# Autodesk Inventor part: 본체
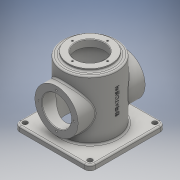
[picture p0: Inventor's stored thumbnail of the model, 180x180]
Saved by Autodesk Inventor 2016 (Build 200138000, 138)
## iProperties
Created: 2019-08
Part Number: 본체
Material: 일반
Document SubType Name: Modeling
Designer: user
Density: 1 g/cm^3
Appearance: 기본값
Author: user
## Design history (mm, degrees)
sketch "스케치1"
  geometry: L1 (70, -70)-(-70, -70); L2 (-70, -70)-(-70, 70); L3 (-70, 70)-(70, 70); L4 (70, 70)-(70, -70); L5 (70, -70)-(-70, 70); L6 (-70, -70)-(70, 70); 1 further point
  constraints: 12 end point, 2 midpoint, 2 parallel, 1 horizontal, 1 perpendicular
  dimensions: "d0" = 140 distance of L2.end L3.end; "d1" = 140 distance of L1.end L2.end
extrude "돌출1" new body sketch "스케치1" distance "d2" = 10; taper "d3" = 0 deg
sketch "스케치2"
  geometry: C1 r 50 at (0, 0); 1 further point
  constraints: 1 centre point, 1 coincident
  dimensions: "d4" = 100 diameter of C1
extrude "돌출2" join sketch "스케치2" distance "d5" = 110; taper "d6" = 0 deg
sketch "스케치3"
  geometry: C1 r 40 at (0, 0); 1 further point
  constraints: 1 centre point, 1 coincident
  dimensions: "d7" = 80 diameter of C1
extrude "돌출3" join sketch "스케치3" distance "d8" = 5; taper "d9" = 0 deg
sketch "스케치6"
  geometry: C1 r 27 at (0, 0); 1 further point
  constraints: 1 centre point, 1 coincident
  dimensions: "d11" = 54 diameter of C1
hole "구멍1" sketch "스케치6" at (0, 0) diameter "d12" = 54; stored, may be unused: countersink angle "d16" = 90 deg, drill point angle "d18" = 0 deg; dims "d13" = 6, "d14" = 4, "d15" = 2, "d17" = 13
node "작업 평면1"
sketch "스케치9"
  geometry: L1 (-70, 0)-(70, 0) reference; C1 r 40 at (0, 60); 2 further points
  constraints: 1 centre point, 1 midpoint, 1 vertical alignment
  dimensions: "d28" = 80 diameter of C1; "d29" = 60 distance from line of L1 C1.centre
extrude "돌출4" join sketch "스케치9" stored distance "d30" = 12; taper "d31" = 0 deg
fillet "모깎기1" dims "d32" = 10
hole "구멍3" diameter "d35" = 9; stored, may be unused: countersink angle "d39" = 90 deg, drill point angle "d41" = 0 deg; dims "d33" = 10, "d34" = 10, "d36" = 6, "d37" = 4, "d38" = 2, "d40" = 112
sketch "스케치12"
  geometry: 2 further points
  constraints: 1 vertical alignment
  dimensions: "d49" = 32.5 distance of point (0, 0) point (0, 32.5)
hole "구멍4" sketch "스케치12" at (0, 32.5) diameter "d50" = 3.242; stored, may be unused: countersink angle "d54" = 90 deg, drill point angle "d56" = 118 deg; dims "d51" = 8, "d52" = 4, "d53" = 2, "d55" = 10
fillet "모깎기2" dims "d60" = 3
fillet "모깎기3" dims "d61" = 3
hole "구멍5" diameter "d64" = 54; stored, may be unused: countersink angle "d68" = 90 deg, drill point angle "d70" = 0 deg; dims "d62" = 10, "d63" = 10, "d65" = 8, "d66" = 4, "d67" = 2, "d69" = 10
sketch "스케치15"
  geometry: C1 r 27 at (0, 0) reference; C2 r 40 at (0, 0) reference; 2 further points
  constraints: 1 vertical alignment
  dimensions: "d71" = 32.5 distance of C1.centre point (0, 32.5)
hole "구멍6" sketch "스케치15" at (0, 32.5) diameter "d72" = 3.242; stored, may be unused: countersink angle "d76" = 90 deg, drill point angle "d78" = 118 deg; dims "d73" = 8, "d74" = 4, "d75" = 2, "d77" = 10
fillet "모깎기4" dims "d82" = 3
chamfer "모따기1" distance "d83" = 1; stored, may be unused: second distance "d84" = 2, angle "d85" = 45 deg
sketch "스케치17"
  geometry: C1 r 45 at (0, 0); 1 further point
  constraints: 1 centre point, 1 coincident
  dimensions: "d86" = 90 diameter of C1
hole "구멍7" sketch "스케치17" at (0, 0) diameter "d87" = 90; stored, may be unused: countersink angle "d91" = 90 deg, drill point angle "d93" = 0 deg; dims "d88" = 8, "d89" = 4, "d90" = 2, "d92" = 112
fillet "모깎기6" dims "d95" = 3
chamfer "모따기2" distance "d96" = 1; stored, may be unused: second distance "d97" = 2, angle "d98" = 45 deg
chamfer "모따기3" distance "d99" = 1; stored, may be unused: second distance "d100" = 2, angle "d101" = 45 deg
fillet "모깎기7" dims "d102" = 3
fillet "모깎기8" dims "d103" = 3
node "작업 평면2"
sketch "스케치23" dims "d0" = 140, "d1" = 140
  geometry: L1 (60, 0)-(-60, 0) reference; 3 further points
  constraints: 1 midpoint, 1 vertical alignment, 1 other
  dimensions: "d105" = 70 distance from line of L1 point (0, 70)
feature "엠보싱1" sketch "스케치23" dims "d106" = 0.5, "d107" = 0
node "솔리드1"
mirror "대칭1"
pattern_linear "직사각형 패턴1" dims "d44" = 120
pattern_circular "원형 패턴1" dims angle "d58" = 360 deg
pattern_circular "원형 패턴2" dims angle "d80" = 360 deg
mirror "대칭2"
node "투영된 루프4"
other parameters: "d27" = -62, "d104" = 64.75
